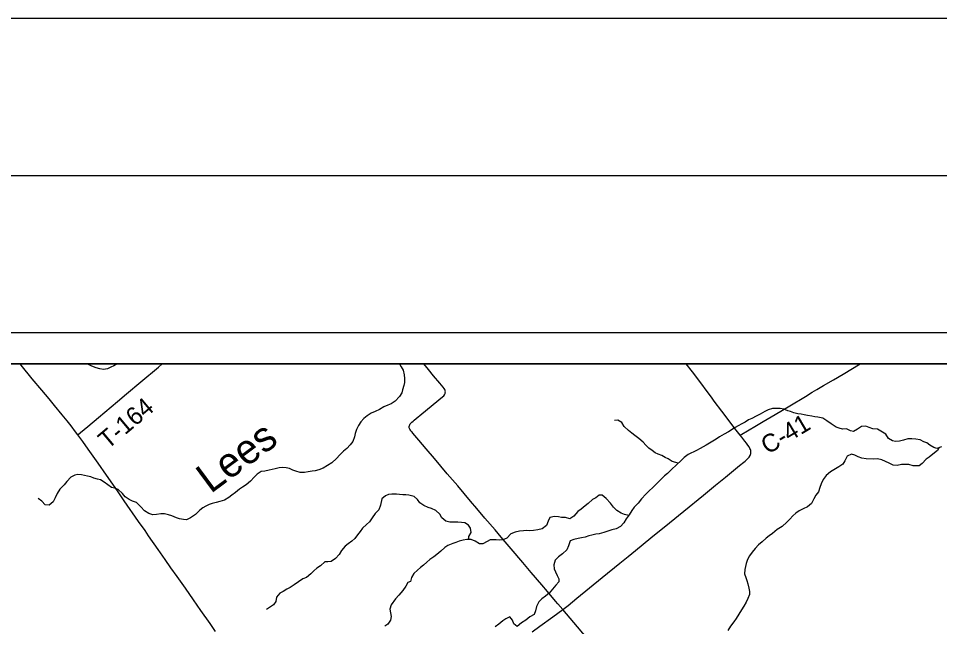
# Model space of a CAD drawing. Extents: x 0 to 34, y 0 to 22.
# Drawn here: x 3.432 to 6.367, y 20.064 to 22 of the extents above; entities that cross this region are included whole.
import ezdxf

# ---------------------------------------------------------------- set-up
doc = ezdxf.new("R2010")
doc.units = 0
for name, color, linetype in [('Default', 7, 'Continuous'), ('GM_X_County_Road', 7, 'Continuous'), ('GM_X_County_Road_Text', 7, 'Continuous'), ('GM_X_Minor_River', 7, 'Continuous'), ('GM_X_Minor_River_Text', 7, 'Continuous'), ('GM_X_State_Route', 7, 'Continuous'), ('GM_X_Township_Road', 7, 'Continuous'), ('GM_X_Township_Road_Text', 7, 'Continuous'), ('SH_Border', 7, 'Continuous'), ('SH_Cut_Line', 7, 'Continuous'), ('SH_Data', 7, 'Continuous')]:
    doc.layers.add(name, color=color, linetype=linetype)

msp = doc.modelspace()

# ---------------------------------------------------------------- linework, layer by layer
at = {"layer": 'Default'}
msp.add_lwpolyline([(6.6858, 19.0362), (6.6949, 19.1537), (6.8302, 20.9), (3.1229, 20.9), (2.9275, 20.8467), (2.2946, 20.6707), (2.1, 20.6202), (2.1, 17.1279), (2.1211, 17.1003), (3.2076, 15.5689), (3.4902, 15.1704), (4.0558, 14.3671), (4.1658, 14.2105), (4.302, 14.3105), (5.6165, 15.2674), (6.0871, 15.6176), (6.2834, 15.7529), (6.4392, 15.8657), (6.5428, 17.1931), (6.5451, 17.2211), (6.6309, 18.3364), (6.6363, 18.3979), (6.6654, 18.7733)], dxfattribs=at)
at = {"layer": 'GM_X_County_Road'}
msp.add_lwpolyline([(5.7315, 20.6727), (5.7367, 20.6759), (5.7547, 20.687), (5.7841, 20.7044), (5.8049, 20.7169), (5.8429, 20.7393), (5.89, 20.767), (5.9403, 20.7967), (5.9615, 20.8096), (5.976, 20.8182), (5.9973, 20.8308), (6.0289, 20.8495), (6.0594, 20.8676), (6.1146, 20.9)], dxfattribs=at)
at = {"layer": 'GM_X_Minor_River'}
for points in [[(3.7466, 20.9), (3.736, 20.8936), (3.7264, 20.8892), (3.7154, 20.884), (3.7028, 20.8822), (3.6914, 20.8846), (3.6796, 20.8874), (3.666, 20.8925), (3.6547, 20.8983), (3.6465, 20.9)], [(4.6459, 20.9), (4.6517, 20.8909), (4.6577, 20.8798), (4.6609, 20.8654), (4.6619, 20.8532), (4.6618, 20.8406), (4.6601, 20.8312), (4.6558, 20.8179), (4.653, 20.8081), (4.6464, 20.7964), (4.6325, 20.7813), (4.6191, 20.7727), (4.6092, 20.7687), (4.5958, 20.7631), (4.582, 20.7549), (4.569, 20.749), (4.5556, 20.7431), (4.5426, 20.7352), (4.5322, 20.7266), (4.5226, 20.7161), (4.5156, 20.7044), (4.5093, 20.6908), (4.505, 20.6783), (4.5026, 20.6677), (4.4975, 20.6529), (4.4886, 20.642), (4.4785, 20.6307), (4.4678, 20.6217), (4.4562, 20.6108), (4.4454, 20.5988), (4.4304, 20.5853), (4.4166, 20.5763), (4.4028, 20.5681), (4.3891, 20.5626), (4.3776, 20.5593), (4.3677, 20.5586), (4.3548, 20.5569), (4.3437, 20.5547), (4.33, 20.5541), (4.316, 20.5581), (4.3061, 20.5616), (4.2952, 20.5667), (4.2853, 20.5687), (4.2728, 20.57), (4.2628, 20.5689), (4.2499, 20.566), (4.2403, 20.5635), (4.2304, 20.5617), (4.2171, 20.5588), (4.2053, 20.557), (4.1926, 20.5492), (4.183, 20.539), (4.1714, 20.5266), (4.1576, 20.5154), (4.1461, 20.5072), (4.1357, 20.5016), (4.1238, 20.4911), (4.1115, 20.4825), (4.1019, 20.4742), (4.0889, 20.4664), (4.074, 20.4624), (4.0614, 20.4591), (4.0496, 20.4558), (4.0396, 20.4521), (4.0293, 20.4473), (4.0194, 20.4421), (4.0094, 20.4339), (3.9959, 20.4207), (3.9798, 20.4095), (3.9672, 20.4039), (3.9577, 20.4044), (3.9451, 20.4065), (3.9349, 20.4104), (3.9201, 20.4166), (3.9099, 20.4194), (3.897, 20.4222), (3.8852, 20.4227), (3.8719, 20.421), (3.8597, 20.42), (3.8468, 20.4239), (3.8336, 20.4317), (3.8216, 20.4451)], [(6.3729, 20.6359), (6.358, 20.6311), (6.3486, 20.6334), (6.3365, 20.6418), (6.3267, 20.6488), (6.3168, 20.6515), (6.3051, 20.658), (6.2914, 20.6604), (6.2789, 20.6616), (6.266, 20.661), (6.2519, 20.6573), (6.2397, 20.6536), (6.2272, 20.6533), (6.2173, 20.6553), (6.2049, 20.6626), (6.1959, 20.6763), (6.1857, 20.6832), (6.1698, 20.6924), (6.1546, 20.6937), (6.1425, 20.6976), (6.1319, 20.7022), (6.1182, 20.7012), (6.1056, 20.6918), (6.0926, 20.685), (6.0832, 20.6874), (6.0703, 20.6928), (6.0574, 20.6925), (6.0472, 20.6953), (6.0373, 20.6991), (6.0214, 20.7095), (6.0082, 20.7183), (5.9946, 20.7272), (5.9791, 20.7303), (5.9692, 20.7315), (5.9597, 20.7335), (5.9461, 20.7359), (5.9358, 20.7375), (5.9256, 20.7398), (5.9154, 20.7414), (5.9025, 20.7442), (5.8926, 20.748), (5.8832, 20.7504), (5.871, 20.7554), (5.8589, 20.7578), (5.8487, 20.7582), (5.8346, 20.758), (5.8209, 20.7543), (5.8106, 20.7486), (5.7954, 20.74), (5.7831, 20.7333), (5.769, 20.7266), (5.758, 20.7217), (5.7473, 20.7146), (5.7374, 20.7093), (5.7252, 20.7026), (5.7157, 20.6977), (5.6943, 20.6842), (5.6809, 20.6767), (5.666, 20.6677), (5.655, 20.6606), (5.6447, 20.6538), (5.634, 20.6482), (5.6237, 20.6418), (5.6142, 20.6362), (5.6039, 20.6306), (5.592, 20.6238), (5.5661, 20.6111), (5.5531, 20.6021), (5.5401, 20.5897), (5.5306, 20.5806), (5.511, 20.5614), (5.5003, 20.5513), (5.4908, 20.5434), (5.4525, 20.5057), (5.4429, 20.4974), (5.4307, 20.485), (5.4177, 20.4702), (5.4062, 20.457), (5.3939, 20.4435), (5.3866, 20.4329), (5.3781, 20.4197), (5.3682, 20.4064), (5.3609, 20.3943), (5.3505, 20.3827), (5.3364, 20.3748), (5.3231, 20.3715), (5.3105, 20.3674), (5.2972, 20.3633), (5.2824, 20.3592), (5.2721, 20.3574), (5.2592, 20.3552)], [(5.5343, 20.5841), (5.5268, 20.5856), (5.5147, 20.5895), (5.5026, 20.5976), (5.4927, 20.6022), (5.4818, 20.6083), (5.4708, 20.6126), (5.461, 20.6168), (5.4508, 20.6238), (5.441, 20.6318), (5.4312, 20.641), (5.4221, 20.6509), (5.4089, 20.6624), (5.3961, 20.6716), (5.3863, 20.6793), (5.3757, 20.6877), (5.3625, 20.7011), (5.3543, 20.7133), (5.3422, 20.721), (5.3315, 20.7196)], [(6.3658, 20.6336), (6.3603, 20.6242), (6.3461, 20.6129), (6.3335, 20.6035), (6.324, 20.5964), (6.3121, 20.5828), (6.3025, 20.5757), (6.2923, 20.5754), (6.2828, 20.5754), (6.2688, 20.5797), (6.2589, 20.5802), (6.2456, 20.5795), (6.2319, 20.5766), (6.219, 20.5774), (6.2061, 20.584), (6.1952, 20.5894), (6.1834, 20.5944), (6.1694, 20.5975), (6.1573, 20.5972), (6.133, 20.5974), (6.1197, 20.5998), (6.1072, 20.6044), (6.0966, 20.6095), (6.086, 20.6122), (6.073, 20.6058), (6.0653, 20.5915), (6.0588, 20.5805), (6.0458, 20.5719), (6.0355, 20.5663), (6.0199, 20.5569), (6.0057, 20.5452), (5.9961, 20.5316), (5.9903, 20.518), (5.9857, 20.5066), (5.9814, 20.4926), (5.9733, 20.4824), (5.966, 20.47), (5.9587, 20.4552), (5.9461, 20.445), (5.932, 20.4383), (5.9194, 20.4323), (5.9091, 20.4244), (5.8995, 20.4165), (5.8899, 20.4052), (5.8804, 20.3958), (5.8658, 20.3826), (5.8494, 20.3729), (5.8349, 20.3604), (5.8246, 20.3526), (5.815, 20.345), (5.802, 20.3337), (5.7898, 20.3243), (5.7798, 20.3119), (5.7702, 20.3009), (5.7618, 20.2889), (5.7549, 20.2775), (5.751, 20.265), (5.7482, 20.2552), (5.7463, 20.2453), (5.7454, 20.2313), (5.7495, 20.2195), (5.7524, 20.2099), (5.7565, 20.1997), (5.7595, 20.1856), (5.7617, 20.1757), (5.7616, 20.1662), (5.7565, 20.1533), (5.7511, 20.1416), (5.7438, 20.1288), (5.7361, 20.1167), (5.7273, 20.1027), (5.7185, 20.0898), (5.7119, 20.0793), (5.7012, 20.0649), (5.6919, 20.0509)], [(3.8216, 20.4451), (3.808, 20.4589), (3.7955, 20.4632), (3.7842, 20.4679), (3.7717, 20.4772), (3.7635, 20.4872), (3.7492, 20.5002), (3.7389, 20.5045), (3.7283, 20.5069), (3.7162, 20.5147), (3.7046, 20.5235), (3.6928, 20.5305), (3.6834, 20.5333), (3.672, 20.5364), (3.6621, 20.54), (3.6523, 20.5424), (3.6424, 20.5444), (3.6322, 20.5468), (3.6215, 20.548), (3.6116, 20.5455), (3.599, 20.5399), (3.5855, 20.526), (3.577, 20.5151), (3.5639, 20.5012), (3.5554, 20.4872), (3.5491, 20.4732), (3.5421, 20.4604), (3.5294, 20.4499), (3.5173, 20.4508), (3.506, 20.4631), (3.4947, 20.4716)], [(4.6759, 20.4818), (4.6666, 20.4834), (4.6571, 20.4828), (4.6465, 20.4837), (4.6366, 20.4849), (4.6218, 20.4851), (4.6115, 20.4841), (4.6019, 20.48), (4.5896, 20.4703), (4.5856, 20.4505), (4.5805, 20.4354), (4.5685, 20.4234), (4.5588, 20.4098), (4.5507, 20.3974), (4.5407, 20.3884), (4.528, 20.3767), (4.521, 20.3665), (4.5122, 20.356), (4.5033, 20.3443), (4.4937, 20.3357), (4.4829, 20.3275), (4.4733, 20.3196), (4.4613, 20.3064), (4.4536, 20.2932), (4.4416, 20.28), (4.4286, 20.2714), (4.4179, 20.27), (4.4084, 20.2694), (4.3938, 20.2574), (4.3827, 20.2499), (4.3731, 20.2417), (4.363, 20.2311), (4.3496, 20.2199), (4.3378, 20.2159), (4.3247, 20.2065), (4.3109, 20.1968), (4.2979, 20.1886), (4.2875, 20.1826), (4.2749, 20.1755), (4.2649, 20.1699), (4.2541, 20.1571), (4.2517, 20.1439), (4.2447, 20.1325), (4.2351, 20.1262), (4.2224, 20.1176)], [(5.3764, 20.4173), (5.3633, 20.4209), (5.352, 20.4248), (5.3391, 20.4329), (5.3282, 20.4436), (5.3188, 20.4565), (5.3049, 20.4711), (5.2921, 20.4826), (5.2826, 20.4819), (5.2722, 20.4732), (5.2612, 20.468), (5.2474, 20.4559), (5.2375, 20.4477), (5.2249, 20.4379), (5.2142, 20.4304), (5.2019, 20.4157), (5.1885, 20.4066), (5.1753, 20.4113), (5.1624, 20.4114), (5.1525, 20.4126), (5.1396, 20.4138), (5.1255, 20.4113), (5.1201, 20.3988), (5.1143, 20.3856), (5.1006, 20.3754), (5.0865, 20.3721), (5.0736, 20.3699), (5.061, 20.3689), (5.0512, 20.3693), (5.0417, 20.369), (5.028, 20.3676), (5.0147, 20.3646), (5.001, 20.3587), (4.9883, 20.3451), (4.9757, 20.3395), (4.9636, 20.3388), (4.9541, 20.3397), (4.9446, 20.3401), (4.9351, 20.3394), (4.9256, 20.3349), (4.9115, 20.3267), (4.9008, 20.3268), (4.8869, 20.3352), (4.874, 20.3406), (4.8611, 20.3407), (4.8489, 20.3385), (4.8363, 20.3352), (4.8261, 20.3315), (4.8158, 20.3285), (4.7998, 20.3222), (4.7902, 20.3158), (4.7776, 20.3038), (4.7654, 20.2928), (4.7558, 20.2861), (4.7432, 20.2771), (4.7329, 20.2684), (4.723, 20.2594), (4.7134, 20.2522), (4.7035, 20.2436), (4.692, 20.2323), (4.6843, 20.2202), (4.6812, 20.2073), (4.6724, 20.2037)], [(4.8675, 20.3407), (4.8672, 20.3506), (4.8742, 20.363), (4.8727, 20.3767), (4.8664, 20.387), (4.8539, 20.3943), (4.8433, 20.3955), (4.8319, 20.3964), (4.819, 20.3957), (4.8061, 20.3966), (4.7932, 20.3993), (4.7811, 20.4104), (4.7751, 20.4215), (4.7619, 20.4337), (4.7479, 20.4399), (4.7377, 20.443), (4.7233, 20.4492), (4.7112, 20.4576), (4.7037, 20.468), (4.6924, 20.4783), (4.6759, 20.4818)], [(5.2592, 20.3552), (5.2496, 20.3527), (5.2375, 20.3489), (5.2257, 20.3464), (5.2158, 20.3438), (5.2017, 20.3412), (5.1903, 20.3364), (5.1845, 20.3212), (5.1794, 20.308), (5.1656, 20.2948), (5.1527, 20.2862), (5.1419, 20.2749), (5.1384, 20.2601), (5.1394, 20.2475), (5.1428, 20.238), (5.1484, 20.2266), (5.154, 20.2159), (5.1536, 20.2064), (5.1444, 20.1955), (5.1332, 20.1827), (5.1233, 20.1706), (5.1118, 20.1604), (5.1, 20.1525), (5.0896, 20.1427), (5.0823, 20.128), (5.0792, 20.1143), (5.0749, 20.1026), (5.0619, 20.0943), (5.0485, 20.0842), (5.0344, 20.0759), (5.021, 20.0635), (5.0105, 20.0723), (5.006, 20.0845), (4.9977, 20.0948), (4.9852, 20.0888), (4.9752, 20.0821), (4.963, 20.0715), (4.9508, 20.0633)], [(4.6724, 20.2037), (4.6658, 20.192), (4.6565, 20.1781), (4.6442, 20.1641), (4.6338, 20.1525), (4.6191, 20.1329), (4.6151, 20.1193), (4.6176, 20.1078), (4.6198, 20.0956), (4.6173, 20.0839), (4.6088, 20.0714), (4.5988, 20.0647)]]:
    msp.add_lwpolyline(points, dxfattribs=at)
at = {"layer": 'GM_X_State_Route'}
for points in [[(4.0598, 20.0484), (4.0425, 20.0734), (4.0134, 20.1153), (3.99, 20.1489), (3.9637, 20.1858), (3.9373, 20.2235), (3.9174, 20.2512), (3.899, 20.277), (3.8768, 20.3092), (3.8467, 20.3527), (3.8355, 20.3691), (3.8148, 20.3986), (3.769, 20.4643), (3.7472, 20.4954), (3.7125, 20.5454), (3.6858, 20.5836), (3.6544, 20.6284), (3.637, 20.6526), (3.6212, 20.6741), (3.6138, 20.6842), (3.5998, 20.7025), (3.5867, 20.719), (3.5712, 20.7376), (3.5462, 20.7678), (3.5292, 20.7884), (3.5063, 20.8162), (3.4757, 20.853), (3.4406, 20.8957), (3.437, 20.9)], [(5.0687, 20.0471), (5.0929, 20.0646), (5.1347, 20.0947), (5.1664, 20.1181), (5.1834, 20.1313), (5.2109, 20.1537), (5.2519, 20.187), (5.2918, 20.2196), (5.3483, 20.2653), (5.3753, 20.2873), (5.3983, 20.3063), (5.4475, 20.3463), (5.5064, 20.3939), (5.5521, 20.4313), (5.6148, 20.4823), (5.6532, 20.5138), (5.6845, 20.5393), (5.7299, 20.5761), (5.7438, 20.5876), (5.7476, 20.5908), (5.7543, 20.5965), (5.7583, 20.6006), (5.7607, 20.6035), (5.7638, 20.6083), (5.7649, 20.6112), (5.7657, 20.6145), (5.7659, 20.6176), (5.7659, 20.6209), (5.7653, 20.6241), (5.7643, 20.6271), (5.7628, 20.6306), (5.7601, 20.6356), (5.7557, 20.6418), (5.7515, 20.6472), (5.7461, 20.6541), (5.7365, 20.6663), (5.7315, 20.6727), (5.7273, 20.678), (5.7147, 20.6949), (5.6969, 20.7189), (5.6736, 20.7496), (5.6493, 20.7818), (5.64, 20.7942), (5.6261, 20.8125), (5.6059, 20.8393), (5.5793, 20.8745), (5.56, 20.9)]]:
    msp.add_lwpolyline(points, dxfattribs=at)
at = {"layer": 'GM_X_Township_Road'}
for points in [[(3.6212, 20.6741), (3.6295, 20.6813), (3.6526, 20.7011), (3.6868, 20.7299), (3.7469, 20.78), (3.7764, 20.8048), (3.8221, 20.8431), (3.8777, 20.89), (3.8896, 20.9)], [(5.1664, 20.1181), (5.151, 20.1359), (5.1437, 20.1444), (5.1181, 20.1749), (5.0996, 20.1966), (5.0658, 20.2363), (5.0388, 20.268), (5.002, 20.311), (4.983, 20.3332), (4.9702, 20.3483), (4.9504, 20.3715), (4.9182, 20.4093), (4.8923, 20.4395), (4.8727, 20.4628), (4.8319, 20.5113), (4.7983, 20.5505), (4.7578, 20.5984), (4.7311, 20.6295), (4.7076, 20.6568), (4.6887, 20.6791), (4.6859, 20.6824), (4.6834, 20.6853), (4.6809, 20.6888), (4.6789, 20.6919), (4.6779, 20.6941), (4.6772, 20.6963), (4.6769, 20.6989), (4.677, 20.701), (4.6777, 20.7039), (4.6787, 20.7064), (4.6801, 20.7088), (4.6816, 20.7106), (4.6852, 20.7141), (4.6895, 20.7176), (4.6933, 20.7208), (4.7058, 20.731), (4.7111, 20.7354), (4.7538, 20.7705), (4.7834, 20.7951), (4.7871, 20.7986), (4.7891, 20.8011), (4.7907, 20.8038), (4.7916, 20.8062), (4.7921, 20.8088), (4.7923, 20.8113), (4.792, 20.8139), (4.7912, 20.8164), (4.7902, 20.8187), (4.7881, 20.8218), (4.7847, 20.8263), (4.7746, 20.8382), (4.7547, 20.862), (4.738, 20.8821), (4.7233, 20.9)], [(5.9015, 19.2573), (5.8758, 19.2875), (5.831, 19.3391), (5.8094, 19.364), (5.739, 19.4452), (5.706, 19.484), (5.6575, 19.5406), (5.6311, 19.5712), (5.6209, 19.5829), (5.5953, 19.6126), (5.5751, 19.6362), (5.5441, 19.6726), (5.5268, 19.693), (5.492, 19.7343), (5.4698, 19.7603), (5.445, 19.7897), (5.4204, 19.8186), (5.3814, 19.8646), (5.3391, 19.9142), (5.3065, 19.9525), (5.2707, 19.9947), (5.2012, 20.0767), (5.1664, 20.1181)]]:
    msp.add_lwpolyline(points, dxfattribs=at)
at = {"layer": 'SH_Border'}
msp.add_lwpolyline([(1.5, 21.5), (33.5, 21.5), (33.5, 0.5), (1.5, 0.5)], close=True, dxfattribs=at)
at = {"layer": 'SH_Cut_Line'}
msp.add_lwpolyline([(0, 0), (34, 0), (34, 22), (0, 22)], close=True, dxfattribs=at)
msp.add_lwpolyline([(6.6858, 19.0362), (6.6949, 19.1537), (6.8302, 20.9), (2.1, 20.9), (2.1, 14.1), (4.022, 14.1), (4.1658, 14.2105), (4.302, 14.3105), (5.6165, 15.2674), (6.0871, 15.6176), (6.2834, 15.7529), (6.4392, 15.8657), (6.5428, 17.1931), (6.5451, 17.2211), (6.6309, 18.3364), (6.6363, 18.3979), (6.6654, 18.7733)], dxfattribs=at)
at = {"layer": 'SH_Data'}
for p, q in [((2, 21), (9, 21)), ((2.1, 20.9), (8.9, 20.9))]:
    msp.add_line(p, q, dxfattribs=at)

# ---------------------------------------------------------------- texts
at = {"layer": 'GM_X_County_Road_Text'}
msp.add_text('C-41', height=0.05682, rotation=30.8458, dxfattribs=at).set_placement((5.8194, 20.6104))
at = {"layer": 'GM_X_Minor_River_Text'}
msp.add_text('Lees', height=0.0947, rotation=36.5512, dxfattribs=at).set_placement((4.0441, 20.4852))
at = {"layer": 'GM_X_Township_Road_Text'}
msp.add_text('T-164', height=0.05682, rotation=40.0251, dxfattribs=at).set_placement((3.7162, 20.6261))

doc.saveas('drawing.dxf')
